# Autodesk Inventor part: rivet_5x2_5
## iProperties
Created: 2011-01
Part Number: rivet_5x2_5
Document SubType Name: Modeling
Designer: eric
Density: 1 g/cm^3
Mass: 0.103083 g
Surface Area: 2.00144 cm^2
Volume: 0.103083 cm^3
Author: eric
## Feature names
1. Base1
